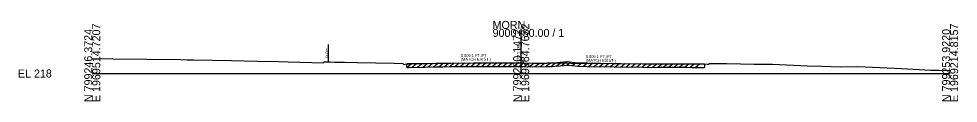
# Model space of a CAD drawing. Extents: x -26 to 2313, y -1511 to 5559.
# Drawn here: x -25.7 to 302.8, y -1009.7 to -981.5 of the extents above; entities that cross this region are included whole.
import ezdxf

# ---------------------------------------------------------------- set-up
doc = ezdxf.new("R2010")
doc.units = 0
for name, color, linetype in [('Default', 7, 'Continuous'), ('RD_XS_ExGround', 7, 'Continuous'), ('RD_XS_ExPaveRet', 7, 'Continuous'), ('RD_XS_ExRW', 7, 'Continuous'), ('RD_XS_Misc_Line', 7, 'Continuous'), ('RD_XS_Pave', 7, 'Continuous'), ('RD_XS_TX_Elev_EX', 7, 'Continuous'), ('RD_XS_TX_Elev_PR', 7, 'Continuous'), ('RD_XS_TX_Slope', 7, 'Continuous')]:
    doc.layers.add(name, color=color, linetype=linetype)

msp = doc.modelspace()

# ---------------------------------------------------------------- linework, layer by layer
at = {"layer": 'Default'}
for p, q in [((150, -1000), (150, -984.39)), ((0, -1000), (150, -1000)), ((150, -1000), (300, -1000))]:
    msp.add_line(p, q, dxfattribs=at)
at = {"layer": 'RD_XS_ExGround'}
msp.add_lwpolyline([(0, -994.8), (7.2, -994.88), (31.02, -995.14), (33.17, -995.21), (35.36, -995.22), (48.68, -995.39), (57.67, -995.67), (65.21, -995.83), (68.48, -995.88), (80.84, -996.23), (80.95, -995.93), (81.48, -995.9), (82.51, -995.9), (83.22, -995.91), (84.73, -996), (86.03, -996.03), (88.18, -996.07), (92.78, -996.17), (105.63, -996.41), (108.68, -996.52), (108.81, -996.82), (109.97, -996.62), (110.85, -996.6), (116.14, -996.48), (120.23, -996.41), (120.99, -996.4), (122.67, -996.38), (125.45, -996.32), (133.27, -996.27), (135.06, -996.26), (137.89, -996.25), (140.87, -996.27), (141.21, -996.28), (141.62, -996.29), (144.46, -996.28), (146.25, -996.31), (148.26, -996.29), (150, -996.28), (150.86, -996.28), (153.83, -996.36), (156.95, -996.32), (157.39, -996.33), (158.98, -996.36), (159.37, -996.31), (160.52, -996.25), (160.89, -996.24), (161.8, -996.23), (163.69, -996.03), (166.03, -995.81), (167.7, -995.97), (169.92, -996.22), (173.11, -996.28), (182.51, -996.45), (192.53, -996.56), (194.27, -996.59), (198.03, -996.58), (206.48, -996.57), (207.85, -996.58), (209.81, -996.6), (211.94, -996.6), (213, -996.61), (213.76, -996.6), (214.08, -996.6), (215.14, -996.72), (215.67, -996.78), (215.79, -996.52), (216.69, -996.51), (220.62, -996.45), (221.87, -996.45), (226.65, -996.58), (231.48, -996.68), (235.05, -996.7), (237.92, -996.69), (250.11, -997.29), (255.05, -997.39), (261.71, -997.64), (267.57, -997.56), (275.6, -997.93), (282.99, -998.25), (293.26, -998.79), (296.07, -998.85), (300, -998.97)], dxfattribs=at)
at = {"layer": 'RD_XS_ExPaveRet'}
for p, q in [((109.97, -997.87), (109.97, -996.62)), ((109.97, -997.87), (110.85, -997.85)), ((110.85, -997.85), (116.14, -997.73)), ((116.14, -997.73), (120.23, -997.66)), ((120.23, -997.66), (120.99, -997.65)), ((120.99, -997.65), (122.67, -997.63)), ((122.67, -997.63), (125.45, -997.57)), ((125.45, -997.57), (133.27, -997.52)), ((133.27, -997.52), (135.06, -997.51)), ((135.06, -997.51), (137.89, -997.5)), ((137.89, -997.5), (140.87, -997.52)), ((140.87, -997.52), (141.21, -997.53)), ((141.21, -997.53), (141.62, -997.54)), ((141.62, -997.54), (144.46, -997.53)), ((144.46, -997.53), (146.25, -997.56)), ((146.25, -997.56), (148.26, -997.54)), ((148.26, -997.54), (150, -997.53)), ((150, -997.53), (150.86, -997.53)), ((150.86, -997.53), (153.83, -997.61)), ((153.83, -997.61), (156.95, -997.57)), ((156.95, -997.57), (157.39, -997.58)), ((157.39, -997.58), (158.98, -997.61)), ((158.98, -997.61), (159.37, -997.56)), ((159.37, -997.56), (160.52, -997.5)), ((160.52, -997.5), (160.89, -997.49)), ((160.89, -997.49), (161.8, -997.48)), ((161.8, -997.48), (163.69, -997.28)), ((163.69, -997.28), (166.03, -997.06)), ((166.03, -997.06), (167.7, -997.22)), ((167.7, -997.22), (169.92, -997.47)), ((169.92, -997.47), (173.11, -997.53)), ((173.11, -997.53), (182.51, -997.7)), ((182.51, -997.7), (192.53, -997.81)), ((192.53, -997.81), (194.27, -997.84)), ((194.27, -997.84), (198.03, -997.83)), ((198.03, -997.83), (206.48, -997.82)), ((206.48, -997.82), (207.85, -997.83)), ((207.85, -997.83), (209.81, -997.85)), ((209.81, -997.85), (211.94, -997.85)), ((211.94, -997.85), (213, -997.86)), ((213, -997.86), (213.76, -997.85)), ((213.76, -997.85), (214.08, -997.85)), ((214.08, -996.6), (214.08, -997.85))]:
    msp.add_line(p, q, dxfattribs=at)
at = {"layer": 'RD_XS_ExRW'}
msp.add_line((82.54, -989.9), (82.54, -995.9), dxfattribs=at)
at = {"layer": 'RD_XS_Misc_Line'}
for p, q in [((109.97, -997.87), (111.56, -996.59)), ((111.83, -997.83), (113.44, -996.55)), ((113.7, -997.79), (115.31, -996.5)), ((115.57, -997.75), (117.17, -996.47)), ((117.44, -997.71), (119.03, -996.43)), ((119.31, -997.68), (120.89, -996.41)), ((121.18, -997.65), (122.77, -996.37)), ((123.04, -997.62), (124.64, -996.34)), ((124.91, -997.58), (126.49, -996.32)), ((126.78, -997.57), (128.35, -996.31)), ((128.65, -997.55), (130.22, -996.29)), ((130.52, -997.54), (132.09, -996.28)), ((132.39, -997.53), (133.96, -996.27)), ((134.25, -997.52), (135.82, -996.26)), ((136.12, -997.51), (137.69, -996.25)), ((137.99, -997.5), (139.53, -996.26)), ((139.86, -997.51), (141.39, -996.28)), ((141.73, -997.54), (143.29, -996.29)), ((143.6, -997.53), (145.14, -996.29)), ((145.47, -997.55), (147.02, -996.3)), ((147.33, -997.55), (148.9, -996.28)), ((149.2, -997.53), (150.76, -996.28)), ((151.07, -997.53), (152.58, -996.33)), ((152.94, -997.59), (154.47, -996.35)), ((154.81, -997.6), (156.39, -996.33)), ((156.68, -997.58), (158.21, -996.34)), ((158.54, -997.6), (160.21, -996.26)), ((160.41, -997.5), (162.02, -996.21)), ((162.28, -997.43), (164.07, -996)), ((164.15, -997.24), (165.91, -995.82)), ((166.02, -997.06), (167.41, -995.94)), ((167.89, -997.24), (169.25, -996.14)), ((169.75, -997.45), (171.26, -996.24)), ((171.62, -997.5), (173.14, -996.28)), ((173.49, -997.54), (175.01, -996.31)), ((175.36, -997.57), (176.88, -996.35)), ((177.23, -997.61), (178.75, -996.38)), ((179.1, -997.64), (180.62, -996.42)), ((180.96, -997.68), (182.49, -996.45)), ((182.83, -997.71), (184.37, -996.47)), ((184.7, -997.73), (186.24, -996.49)), ((186.57, -997.75), (188.11, -996.51)), ((188.44, -997.77), (189.98, -996.53)), ((190.31, -997.78), (191.84, -996.55)), ((192.17, -997.8), (193.7, -996.58)), ((194.04, -997.83), (195.6, -996.58)), ((195.91, -997.83), (197.47, -996.58)), ((197.78, -997.83), (199.34, -996.58)), ((199.65, -997.83), (201.21, -996.58)), ((201.52, -997.83), (203.08, -996.57)), ((203.38, -997.82), (204.95, -996.57)), ((205.25, -997.82), (206.81, -996.57)), ((207.12, -997.82), (208.66, -996.59)), ((208.99, -997.84), (210.53, -996.6)), ((210.86, -997.85), (212.41, -996.6))]:
    msp.add_line(p, q, dxfattribs=at)
at = {"layer": 'RD_XS_Pave'}
for q in [(109.97, -996.62), (202.26, -996.57)]:
    msp.add_line((150, -996.25), q, dxfattribs=at)

# ---------------------------------------------------------------- texts
at = {"layer": 'Default'}
for s, p in [('MORN', (140, -984.39)), ('9000+50.00 / 1', (140, -987.19)), ('EL 218', (-26, -1001.4))]:
    msp.add_text(s, height=2.8, dxfattribs=at).set_placement(p)
for s, p in [('N 799246.3724', (0, -1010)), ('E 1969514.7207', (2.8, -1010)), ('N 799250.1472', (150, -1010)), ('E 1969364.7682', (152.8, -1010)), ('N 799253.9220', (300, -1010)), ('E 1969214.8157', (302.8, -1010))]:
    msp.add_text(s, height=2.8, rotation=90, dxfattribs=at).set_placement(p)
at = {"layer": 'RD_XS_ExRW'}
msp.add_text('Ex. R/W ', height=0.65, rotation=90, dxfattribs=at).set_placement((82.29, -994.52))
at = {"layer": 'RD_XS_TX_Elev_EX'}
msp.add_text('221.72', height=1, rotation=90, dxfattribs=at).set_placement((151.01, -996.28))
at = {"layer": 'RD_XS_TX_Elev_PR'}
msp.add_text(' 221.75', height=1.5, rotation=90, dxfattribs=at).set_placement((150, -996.25))
at = {"layer": 'RD_XS_TX_Slope'}
for s, rotation, p in [('0.009:1 FT./FT.', 360, (128.85, -994.2)), ('(MATCH EXIST.)', 360, (128.85, -995.51)), ('0.006:1 FT./FT.', 359.1819, (172.57, -994.53)), ('(MATCH EXIST.)', 359.1819, (172.55, -995.84))]:
    msp.add_text(s, height=1, rotation=rotation, dxfattribs=at).set_placement(p)

doc.saveas('drawing.dxf')
